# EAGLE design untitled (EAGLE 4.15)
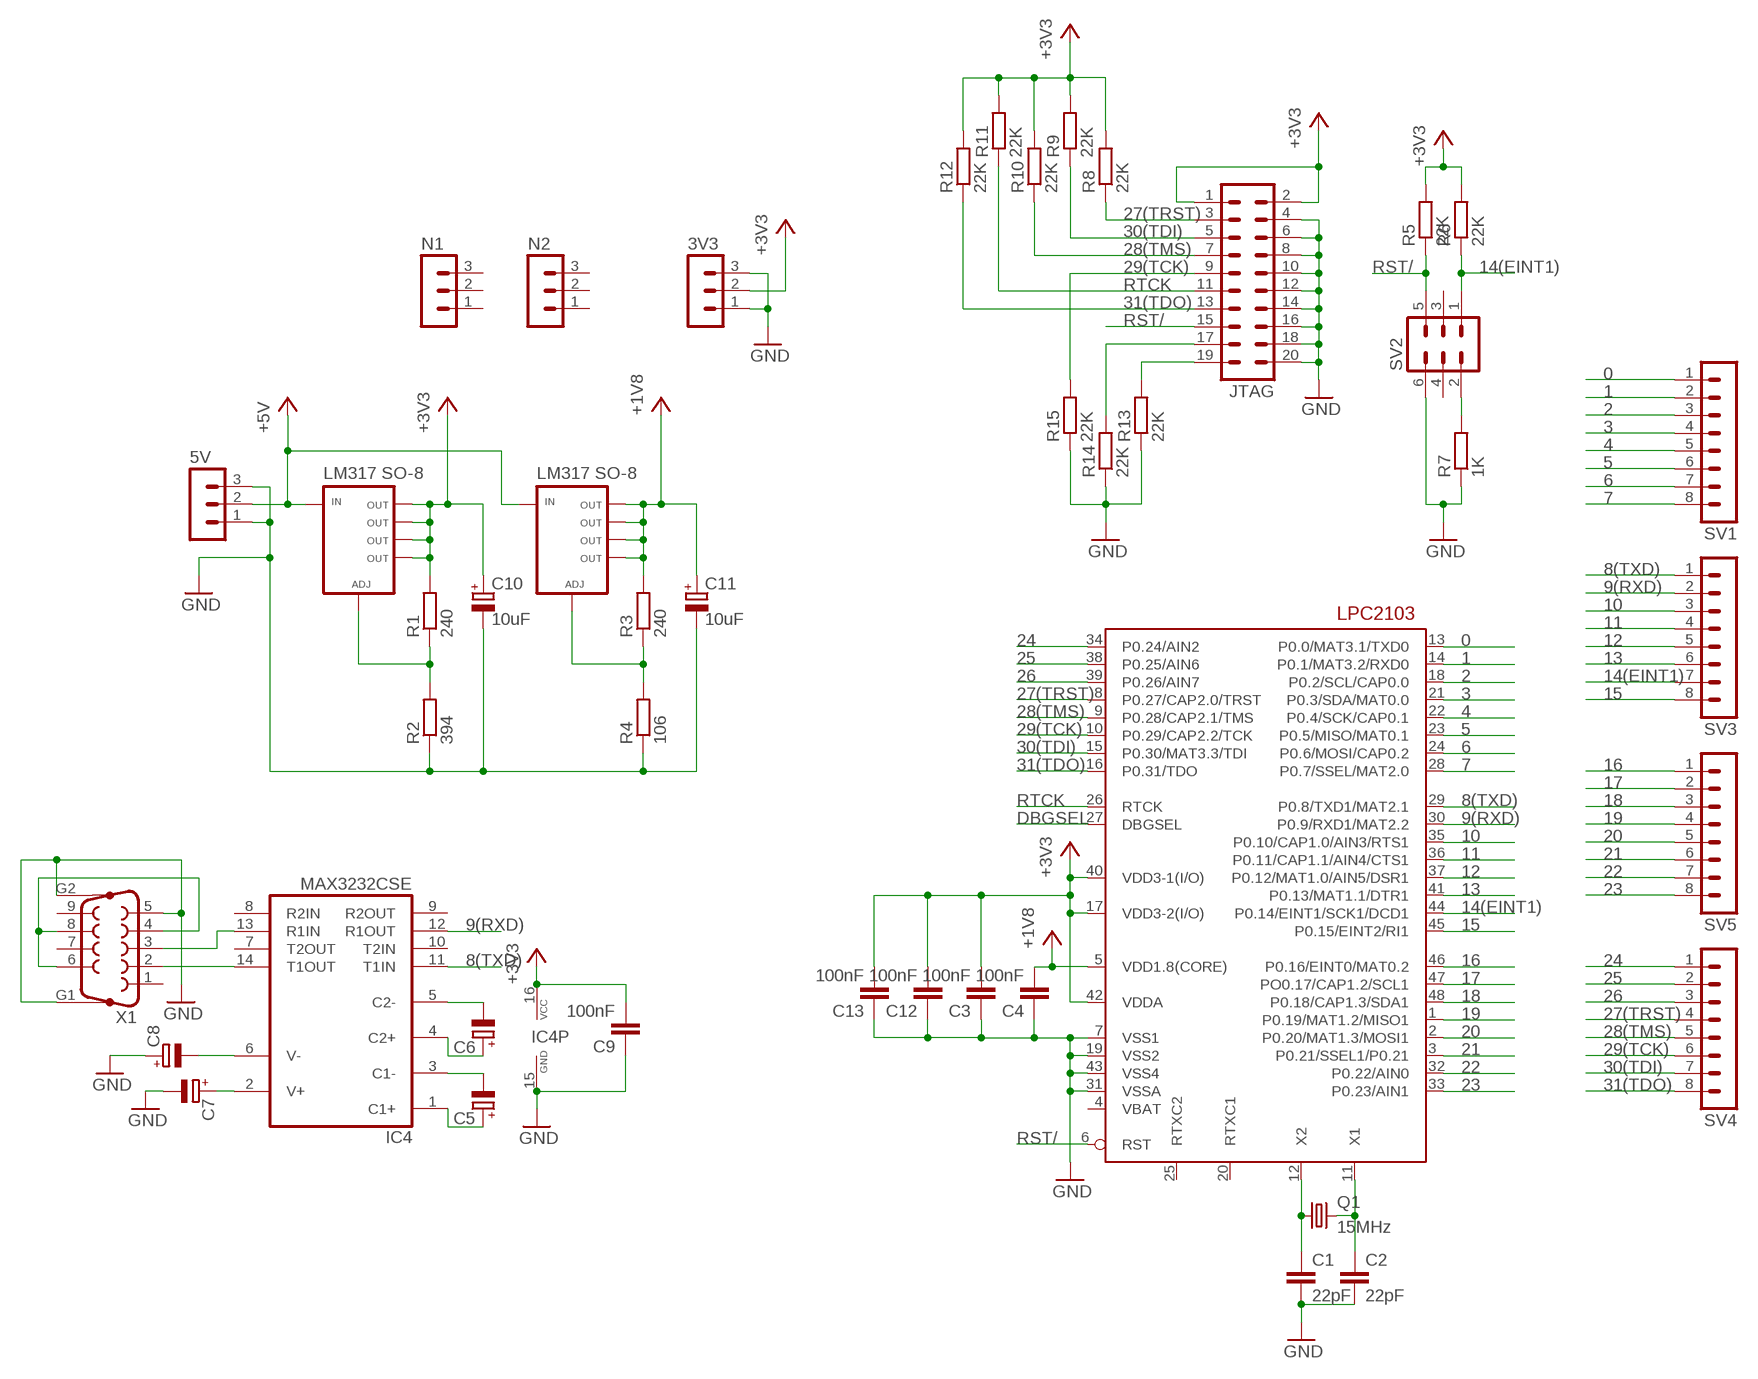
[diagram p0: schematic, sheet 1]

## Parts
3V3  MA03-1  [MA03-1]
5V  MA03-1  [MA03-1]
C1  22pF  C-EUC1206  [C1206]
C2  22pF  C-EUC1206  [C1206]
C3  100nF  C-EUC1206  [C1206]
C4  100nF  C-EUC1206  [C1206]
C5  CPOL-EUE2.5-5  [E2,5-5]
C6  CPOL-EUE2.5-5  [E2,5-5]
C7  CPOL-EUE2.5-5  [E2,5-5]
C8  CPOL-EUE2.5-5  [E2,5-5]
C9  100nF  C-EUC1206  [C1206]
C10  10uF  CPOL-EUE2.5-5  [E2,5-5]
C11  10uF  CPOL-EUE2.5-5  [E2,5-5]
C12  100nF  C-EUC1206  [C1206]
C13  100nF  C-EUC1206  [C1206]
IC1  LPC2103ROUND  [LQFP48ROUND]
IC4  MAX3232CSE  [SO16]
JTAG  MA10-2  [MA10-2]
N1  MA03-1  [MA03-1]
N2  MA03-1  [MA03-1]
Q1  15MHz  CRYTALHC49S  [HC49/S]
R1  240  R-EU_M1206  [M1206]
R2  394  R-EU_M1206  [M1206]
R3  240  R-EU_M1206  [M1206]
R4  106  R-EU_M1206  [M1206]
R5  22K  R-EU_M1206  [M1206]
R6  22K  R-EU_M1206  [M1206]
R7  1K  R-EU_M1206  [M1206]
R8  22K  R-EU_M1206  [M1206]
R9  22K  R-EU_M1206  [M1206]
R10  22K  R-EU_M1206  [M1206]
R11  22K  R-EU_M1206  [M1206]
R12  22K  R-EU_M1206  [M1206]
R13  22K  R-EU_M1206  [M1206]
R14  22K  R-EU_M1206  [M1206]
R15  22K  R-EU_M1206  [M1206]
SV1  MA08-1  [MA08-1]
SV2  MA03-2  [MA03-2]
SV3  MA08-1  [MA08-1]
SV4  MA08-1  [MA08-1]
SV5  MA08-1  [MA08-1]
U$2  LM317  [SO-8]
U$3  LM317  [SO-8]
X1  F09HP  [F09HP]

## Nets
0: IC1.13(P0.0/MAT3.1/TXD0) SV1.1
1: IC1.14(P0.1/MAT3.2/RXD0) SV1.2
2: IC1.18(P0.2/SCL/CAP0.0) SV1.3
3: IC1.21(P0.3/SDA/MAT0.0) SV1.4
4: IC1.22(P0.4/SCK/CAP0.1) SV1.5
5: IC1.23(P0.5/MISO/MAT0.1) SV1.6
6: IC1.24(P0.6/MOSI/CAP0.2) SV1.7
7: IC1.28(P0.7/SSEL/MAT2.0) SV1.8
8(TXD): IC1.29(P0.8/TXD1/MAT2.1) IC4.11(T1IN) SV3.1
9(RXD): IC1.30(P0.9/RXD1/MAT2.2) IC4.12(R1OUT) SV3.2
10: IC1.35(P0.10/CAP1.0/AIN3/RTS1) SV3.3
11: IC1.36(P0.11/CAP1.1/AIN4/CTS1) SV3.4
12: IC1.37(P0.12/MAT1.0/AIN5/DSR1) SV3.5
13: IC1.41(P0.13/MAT1.1/DTR1) SV3.6
14(EINT1): IC1.44(P0.14/EINT1/SCK1/DCD1) R6.1 SV2.1 SV3.7
15: IC1.45(P0.15/EINT2/RI1) SV3.8
16: IC1.46(P0.16/EINT0/MAT0.2) SV5.1
17: IC1.47(PO0.17/CAP1.2/SCL1) SV5.2
18: IC1.48(P0.18/CAP1.3/SDA1) SV5.3
19: IC1.1(P0.19/MAT1.2/MISO1) SV5.4
20: IC1.2(P0.20/MAT1.3/MOSI1) SV5.5
21: IC1.3(P0.21/SSEL1/P0.21) SV5.6
22: IC1.32(P0.22/AIN0) SV5.7
23: IC1.33(P0.23/AIN1) SV5.8
24: IC1.34(P0.24/AIN2) SV4.1
25: IC1.38(P0.25/AIN6) SV4.2
26: IC1.39(P0.26/AIN7) SV4.3
27(TRST): IC1.8(P0.27/CAP2.0/TRST) JTAG.3 R8.1 SV4.4
28(TMS): IC1.9(P0.28/CAP2.1/TMS) JTAG.7 R10.1 SV4.5
29(TCK): IC1.10(P0.29/CAP2.2/TCK) JTAG.9 R15.2 SV4.6
30(TDI): IC1.15(P0.30/MAT3.3/TDI) JTAG.5 R9.1 SV4.7
31(TDO): IC1.16(P0.31/TDO) JTAG.13 R12.1 SV4.8
+1V8: C4.2 C11.+ IC1.5(VDD1.8(CORE)) R3.2 U$3.2(OUT) U$3.3(OUT1) U$3.6(OUT2) U$3.7(OUT3)
+3V3: 3V3.2 C3.2 C9.2 C10.+ C12.2 C13.2 IC1.17(VDD3-2(I/O)) IC1.40(VDD3-1(I/O)) IC1.42(VDDA) IC4.16(VCC) JTAG.1 JTAG.2 R1.2 R5.2 R6.2 R8.2 R9.2 R10.2 R11.2 R12.2 U$2.2(OUT) U$2.3(OUT1) U$2.6(OUT2) U$2.7(OUT3)
+5V: 5V.2 U$2.1(IN) U$3.1(IN)
DBGSEL: IC1.27(DBGSEL)
GND: 3V3.1 3V3.3 5V.1 5V.3 C1.2 C2.2 C3.1 C4.1 C7.- C8.+ C9.1 C10.- C11.- C12.1 C13.1 IC1.7(VSS1) IC1.19(VSS2) IC1.31(VSSA) IC1.43(VSS4) IC4.15(GND) JTAG.4 JTAG.6 JTAG.8 JTAG.10 JTAG.12 JTAG.14 JTAG.16 JTAG.18 JTAG.20 R2.1 R4.1 R7.1 R13.1 R14.1 R15.1 SV2.6 X1.5 X1.G1 X1.G2
GND.: JTAG.17 R14.2
GND..: JTAG.19 R13.2
N$1: C1.1 IC1.12(X2) Q1.1
N$2: C2.1 IC1.11(X1) Q1.2
N$5: R3.1 R4.2 U$3.4(ADJ)
N$6: C5.+ IC4.1(C1+)
N$7: R1.1 R2.2 U$2.4(ADJ)
N$8: C5.- IC4.3(C1-)
N$9: C6.- IC4.5(C2-)
N$10: C6.+ IC4.4(C2+)
N$11: C8.- IC4.6(V-)
N$12: C7.+ IC4.2(V+)
N$13: IC4.14(T1OUT) X1.2
N$14: IC4.13(R1IN) X1.3
N$15: X1.4 X1.6 X1.8
N$19: R7.2 SV2.2
RST/: IC1.6(RST) JTAG.15 R5.1 SV2.5
RTCK: IC1.26(RTCK) JTAG.11 R11.1
Unconnected: IC1.4(VBAT) IC1.20(RTXC1) IC1.25(RTXC2) IC4.7(T2OUT) IC4.8(R2IN) IC4.9(R2OUT) IC4.10(T2IN) N1.1 N1.2 N1.3 N2.1 N2.2 N2.3 SV2.3 SV2.4 X1.1 X1.7 X1.9

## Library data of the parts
3V3 5V N1 N2 = con-lstb:MA03-1: PIN HEADER
C1-C4 C9 C12 C13 = rcl:C-EU: CAPACITOR, European symbol
C5-C8 C10 C11 = rcl:CPOL-EU: POLARIZED CAPACITOR, European symbol
IC1 = nxp:LPC2103: LPC2101/2102/2103 microcontroler from Philips
IC4 = maxim:MAX3232*: True RS-232 Transceivers 3.0V to 5.5V, Low-Power up to 1Mbps, Using Four 0.1µF External Capacitors Source: http://pdfserv.maxim-ic.com/en/ds/MAX3222-MAX3241.pdf
JTAG = con-lstb:MA10-2: PIN HEADER
Q1 = crystal:CRYTAL: CRYSTAL
R1-R15 = rcl:R-EU_: RESISTOR, European symbol
SV1 SV3-SV5 = con-lstb:MA08-1: PIN HEADER
SV2 = con-lstb:MA03-2: PIN HEADER
U$2 U$3 = Steffi:LM317
X1 = con-subd:F09HP: SUB-D

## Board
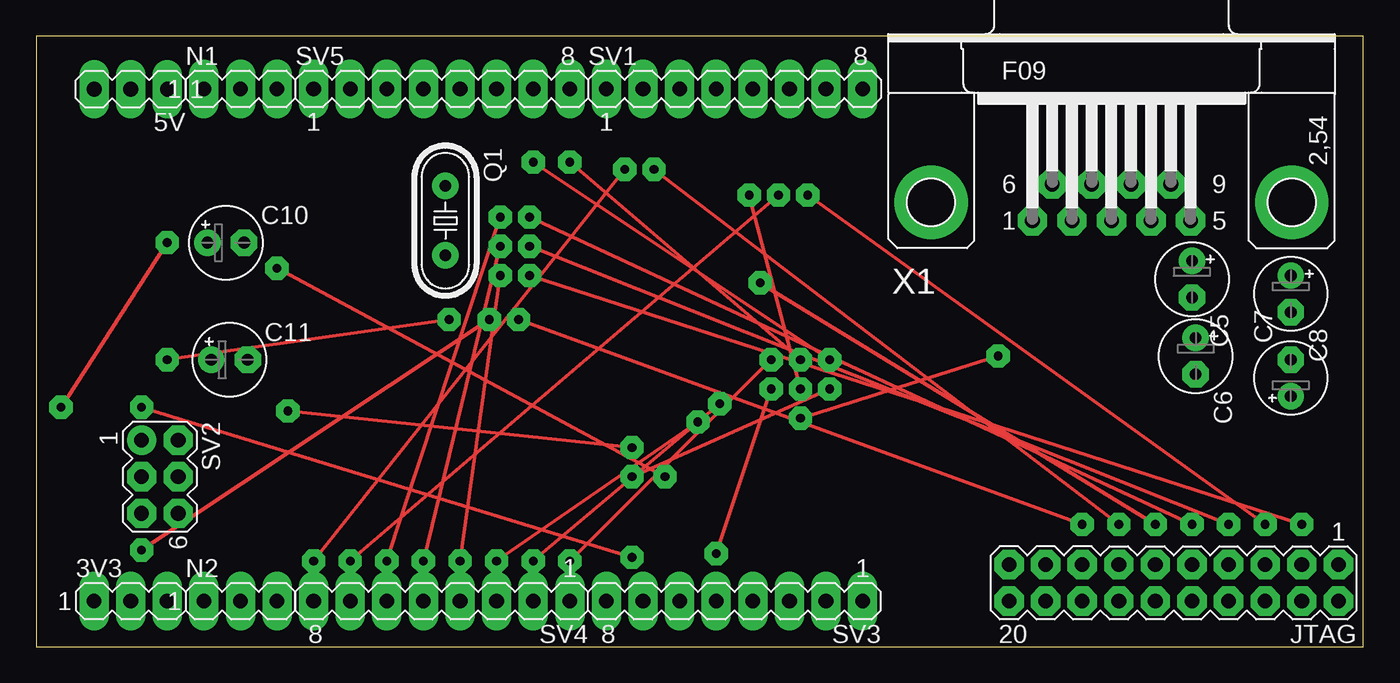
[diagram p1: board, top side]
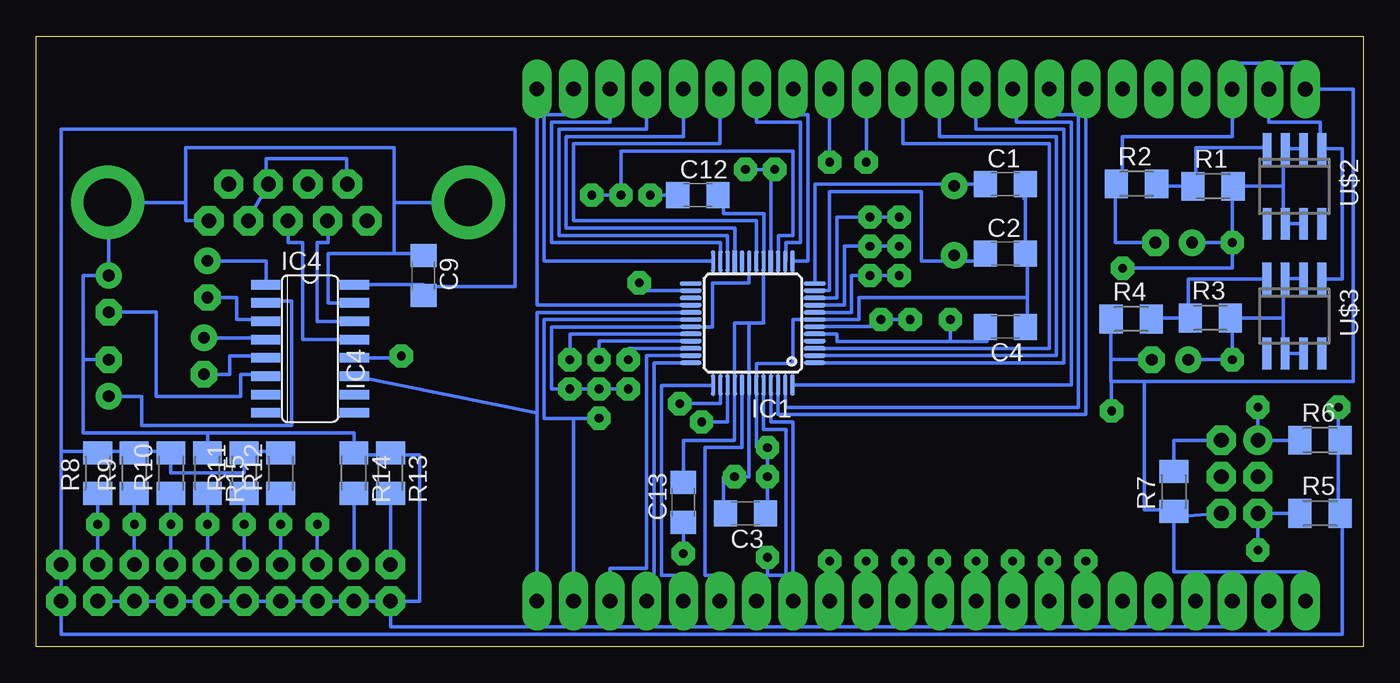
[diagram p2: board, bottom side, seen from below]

Size 92.13 x 42.41 mm. Coordinates in mm from the lower left corner, seen from the top.
Outline: 0,0 92.13,0 92.13,42.41 0,42.41 0,0
Copper layers (1*16): Top 0.035mm / dielectric 1.5mm / Bottom 0.035mm
Design rules "default": minimum track width 10mil, minimum drill 24mil, track to track 8mil, track to pad 8mil, pad to pad 8mil, via to via 8mil, smd to smd 8mil, copper to edge 10mil, drill to drill 10mil, minimum pad ring 20mil, minimum via ring 20mil, stop-mask expansion 4mil, vias tented up to drill 0mil, thermal gap 10mil

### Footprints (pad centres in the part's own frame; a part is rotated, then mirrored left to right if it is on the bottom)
MA03-1 = drill 1.016 long: 1 -2.54,0; 2 0,0; 3 2.54,0
C1206 = smd 1.6 x 1.8: 1 -1.4,0; 2 1.4,0
E2,5-5 = drill 0.813 pad 1.6 round: + -1.27,0 | drill 0.813 pad 1.6 octagon: - 1.27,0
LQFP48ROUND = smd 1.5 x 0.3: 1 -4.3,2.75; 2 -4.3,2.25; 3 -4.3,1.75; 4 -4.3,1.25; 5 -4.3,0.75; 6 -4.3,0.25; 7 -4.3,-0.25; 8 -4.3,-0.75; 9 -4.3,-1.25; 10 -4.3,-1.75; 11 -4.3,-2.25; 12 -4.3,-2.75; 25 4.3,-2.75; 26 4.3,-2.25; 27 4.3,-1.75; 28 4.3,-1.25; 29 4.3,-0.75; 30 4.3,-0.25; 31 4.3,0.25; 32 4.3,0.75; 33 4.3,1.25; 34 4.3,1.75; 35 4.3,2.25; 36 4.3,2.75 | smd 0.3 x 1.5: 13 -2.75,-4.3; 14 -2.25,-4.3; 15 -1.75,-4.3; 16 -1.25,-4.3; 17 -0.75,-4.3; 18 -0.25,-4.3; 19 0.25,-4.3; 20 0.75,-4.3; 21 1.25,-4.3; 22 1.75,-4.3; 23 2.25,-4.3; 24 2.75,-4.3; 37 2.75,4.3; 38 2.25,4.3; 39 1.75,4.3; 40 1.25,4.3; 41 0.75,4.3; 42 0.25,4.3; 43 -0.25,4.3; 44 -0.75,4.3; 45 -1.25,4.3; 46 -1.75,4.3; 47 -2.25,4.3; 48 -2.75,4.3
SO16 = smd 0.66 x 2.032: 1 -4.445,-3.073; 2 -3.175,-3.073; 3 -1.905,-3.073; 4 -0.635,-3.073; 5 0.635,-3.073; 6 1.905,-3.073; 7 3.175,-3.073; 8 4.445,-3.073; 9 4.445,3.073; 10 3.175,3.073; 11 1.905,3.073; 12 0.635,3.073; 13 -0.635,3.073; 14 -1.905,3.073; 15 -3.175,3.073; 16 -4.445,3.073
MA10-2 = drill 1.016 octagon: 1 -11.43,-1.27; 2 -11.43,1.27; 3 -8.89,-1.27; 4 -8.89,1.27; 5 -6.35,-1.27; 6 -6.35,1.27; 7 -3.81,-1.27; 8 -3.81,1.27; 9 -1.27,-1.27; 10 -1.27,1.27; 11 1.27,-1.27; 12 1.27,1.27; 13 3.81,-1.27; 14 3.81,1.27; 15 6.35,-1.27; 16 6.35,1.27; 17 8.89,-1.27; 18 8.89,1.27; 19 11.43,-1.27; 20 11.43,1.27
HC49/S = drill 0.813 round: 1 -2.413,0; 2 2.413,0
M1206 = smd 1.6 x 2: 1 -1.4,0; 2 1.4,0
MA08-1 = drill 1.016 long: 1 -8.89,0; 2 -6.35,0; 3 -3.81,0; 4 -1.27,0; 5 1.27,0; 6 3.81,0; 7 6.35,0; 8 8.89,0
MA03-2 = drill 1.016 round: 1 -2.54,-1.27 | drill 1.016 octagon: 2 -2.54,1.27; 3 0,-1.27; 4 0,1.27; 5 2.54,-1.27; 6 2.54,1.27
SO-8 = smd 0.6 x 2.2: 1 -1.905,-2.6; 2 -0.635,-2.6; 3 0.635,-2.6; 4 1.905,-2.6; 5 1.905,2.6; 6 0.635,2.6; 7 -0.635,2.6; 8 -1.905,2.6
F09HP = drill 1.016 octagon: 1 -5.486,-1.27; 2 -2.743,-1.27; 3 0,-1.27; 4 2.743,-1.27; 5 5.486,-1.27; 6 -4.115,1.27; 7 -1.372,1.27; 8 1.372,1.27; 9 4.115,1.27 | drill 3.302 pad 5.08 round: G1 -12.522,0; G2 12.522,0

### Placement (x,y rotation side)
3V3  6.57,3.17 0 top
5V  6.57,38.71 180 top
C1  24.85,32.13 0 bottom
C2  24.85,27.3 0 bottom
C3  42.89,9.27 180 bottom
C4  24.85,22.22 180 bottom
C5  80.23,25.52 270 top
C6  80.48,20.19 270 top
C7  87.08,18.66 90 top
C8  87.08,24.51 270 top
C9  65.24,25.78 270 bottom
C10  13.17,28.06 0 top
C11  13.42,19.93 0 top
C12  46.19,31.36 0 bottom
C13  47.21,10.03 90 bottom
IC1  42.38,22.47 180 bottom
IC4  73.11,20.7 270 bottom
JTAG  78.96,4.44 180 top
N1  14.19,38.73 0 top
N2  14.19,3.17 0 top
Q1  28.41,29.59 270 top
R1  10.45,31.97 0 bottom
R2  15.76,32.14 0 bottom
R3  10.63,22.83 0 bottom
R4  16.12,22.75 0 bottom
R5  3.01,9.27 0 bottom
R6  3.01,14.35 0 bottom
R7  13.17,10.79 90 bottom
R8  87.85,12.06 90 bottom
R9  85.31,12.06 90 bottom
R10  82.77,12.06 90 bottom
R11  77.69,12.06 90 bottom
R12  75.15,12.06 90 bottom
R13  67.53,12.06 270 bottom
R14  70.07,12.06 270 bottom
R15  80.23,12.06 270 bottom
SV1  48.48,38.73 0 top
SV2  8.6,11.81 270 top
SV3  48.48,3.17 180 top
SV4  28.16,3.17 180 top
SV5  28.16,38.73 0 top
U$2  4.8,31.98 180 bottom
U$3  4.8,22.97 180 bottom
X1  74.64,30.86 0 top

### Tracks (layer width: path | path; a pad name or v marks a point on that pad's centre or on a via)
0
  Bottom 0.254: 39.63,38.73 SV1.1 39.59,36.95 38.57,36.95 38.57,26.77 IC1.13
1
  Bottom 0.254: SV1.2 42.13,36.44 39.08,36.44 39.08,28.06 40.09,28.06 40.09,26.77 IC1.14
2
  Bottom 0.254: IC1.18 42.13,29.59 54.83,29.59 54.83,34.92 44.67,34.92 SV1.3
3
  Bottom 0.254: IC1.21 43.63,29.08 55.33,29.08 55.33,35.43 47.21,35.43 SV1.4
4
  Bottom 0.254: IC1.22 44.13,28.57 55.84,28.57 55.84,35.94 49.75,35.94 SV1.5 49.75,38.98
5
  Bottom 0.254: IC1.23 44.63,28.06 56.35,28.06 56.35,36.44 52.29,36.44 SV1.6
6
  Bottom 0.254: IC1.24 45.13,26.79 56.86,26.79 56.86,36.95 54.83,36.95 SV1.7
7
  Bottom 0.254: IC1.28 57.37,23.72 SV1.8
8(TXD)
  Bottom 0.254: IC1.29 57.37,23.22 57.37,16.12 | SV3.1 57.37,16.12 | IC4.11 57.37,16.25 57.37,16.12
9(RXD)  (via drill 0.6)
  Top 0.254: v53.05,15.87 v66.76,20.19
  Bottom 0.254: IC1.30 56.35,22.72 56.35,22.73 56.86,22.73 56.86,15.87 54.83,15.87 | SV3.2 54.83,15.87 | IC4.12 66.76,20.06 v66.76,20.19 | 54.83,15.87 v53.05,15.87
10
  Bottom 0.254: IC1.35 49.75,20.22 49.75,5.46 52.29,5.46 SV3.3
11
  Bottom 0.254: IC1.36 49.24,19.72 49.24,4.95 49.75,4.95 SV3.4
12
  Bottom 0.254: IC1.37 45.13,18.16 48.73,18.16 48.73,4.95 47.21,4.95 SV3.5
13
  Bottom 0.254: IC1.41 43.13,13.84 45.68,13.84 45.68,4.95 44.92,4.95 44.92,3.17 SV3.6
14(EINT1)  (via drill 0.6 pad 0.25)
  Top 0.254: v7.33,16.63 v41.36,6.22
  Bottom 0.254: R6.1 SV2.1 v7.33,16.63 | IC1.44 41.63,15.11 40.09,15.11 40.09,4.95 41.36,4.95 | 41.36,4.95 42.13,4.95 SV3.7 | v41.36,6.22 41.36,4.95
15
  Bottom 0.254: IC1.45 41.13,15.62 39.59,15.62 SV3.8
16
  Bottom 0.254: IC1.46 40.63,16.12 19.27,16.12 SV5.1
17
  Bottom 0.254: IC1.47 40.13,16.63 19.77,16.63 19.77,36.95 21.81,36.95 SV5.2
18
  Bottom 0.254: IC1.48 20.28,18.17 20.28,36.44 24.09,36.44 24.09,38.73 SV5.3
19
  Bottom 0.254: IC1.1 20.79,19.72 20.79,35.94 26.89,35.94 SV5.4
20
  Bottom 0.254: IC1.2 21.3,20.22 21.3,35.43 29.43,35.43 SV5.5
21
  Bottom 0.254: IC1.3 31.97,20.72 30.44,20.7 21.81,20.7 21.81,34.92 31.97,34.92 SV5.6
22  (via drill 0.6)
  Top 0.254: v55.08,19.93 v34.51,33.65
  Bottom 0.254: IC1.32 55.08,21.71 v55.08,19.93 | v34.51,33.65 SV5.7
23  (via drill 0.6)
  Top 0.254: v53.05,19.93 v37.05,33.65
  Bottom 0.254: IC1.33 53.05,21.22 v53.05,19.93 | v37.05,33.65 SV5.8
24  (via drill 0.6)
  Top 0.254: v37.05,5.96 v51.02,19.93
  Bottom 0.254: IC1.34 51.02,20.72 v51.02,19.93 | SV4.1 v37.05,5.96
25  (via drill 0.6)
  Top 0.254: v34.51,5.96 v47.46,16.89
  Bottom 0.254: 34.51,2.92 SV4.2 v34.51,5.96 | IC1.38 44.63,16.89 v47.46,16.89
26  (via drill 0.6)
  Top 0.254: v31.97,5.96 v45.94,15.62
  Bottom 0.254: IC1.39 44.13,15.62 v45.94,15.62 | SV4.3 v31.97,5.96
27(TRST)  (via drill 0.6)
  Top 0.254: v29.43,5.96 v32.22,25.78 | v34.25,25.78 v87.85,8.5
  Bottom 0.254: JTAG.3 v87.85,8.5 R8.1 | SV4.4 v29.43,5.96 | IC1.8 35.52,23.22 35.52,25.78 v34.25,25.78 v32.22,25.78
28(TMS)  (via drill 0.6)
  Top 0.254: v26.89,5.96 v32.22,27.81 | v34.25,27.81 v82.77,8.5
  Bottom 0.254: JTAG.7 v82.77,8.5 R10.1 | SV4.5 v26.89,5.96 | IC1.9 36.03,23.72 36.03,27.81 v34.25,27.81 v32.22,27.81
29(TCK)  (via drill 0.6)
  Top 0.254: v24.35,5.96 v32.22,29.84 | v34.25,29.84 v80.23,8.5
  Bottom 0.254: JTAG.9 v80.23,8.5 R15.2 | SV4.6 v24.35,5.96 | IC1.10 36.54,24.22 36.54,29.84 v34.25,29.84 v32.22,29.84
30(TDI)  (via drill 0.6)
  Top 0.254: v21.81,5.96 v51.52,31.36 | v53.56,31.36 v85.31,8.5
  Bottom 0.254: v85.31,8.5 JTAG.5 | SV4.7 v21.81,5.96 | v85.31,8.5 R9.1 v85.31,8.5 | v53.56,31.36 v51.52,31.36 51.52,34.41 39.59,34.41 39.59,28.57 40.6,28.57 40.6,26.77 IC1.15
31(TDO)  (via drill 0.6)
  Top 0.254: v19.27,5.96 v40.86,33.14 | v42.89,33.14 v75.15,8.5
  Bottom 0.254: JTAG.13 v75.15,8.5 R12.1 | 41.13,33.14 IC1.16 | 41.13,33.14 v42.89,33.14 | SV4.8 v19.27,5.96 | v40.86,33.14 41.13,33.14
+1V8  (via drill 0.6, 0.6 pad 0.25)
  Top 0.254: v9.11,19.93 v28.66,22.73
  Bottom 0.254: U$3.2 U$3.3 5.55,25.57 5.55,22.73 | U$3.7 U$3.6 5.55,20.37 | 5.55,20.37 5.55,20.44 | 5.55,20.37 5.55,22.73 | 5.55,22.73 5.55,22.83 R3.2 9.11,22.83 v9.11,19.93 C11.+ | IC1.5 36.54,21.72 36.54,21.2 28.66,21.2 | C4.2 26.12,22.22 26.12,21.2 28.66,21.2 | v28.66,22.73 28.66,21.2
+3V3  (via drill 0.6)
  Top 0.254: v1.74,16.63 v9.11,28.06 | v16.73,26.28 v43.65,11.81
  Bottom 0.254: U$2.2 U$2.3 5.55,34.57 | U$2.7 U$2.6 5.55,29.38 | 5.55,29.38 5.55,29.33 | 5.55,34.57 5.55,34.67 | 5.55,32.13 5.55,29.38 | 5.55,32.13 5.55,34.57 | 5.55,32.13 5.55,31.97 R1.2 9.11,31.97 v9.11,28.06 | 1.74,14.35 R6.2 | 1.74,14.35 1.74,9.27 R5.2 1.49,9.27 1.49,0.88 6.57,0.88 | 69.81,25.14 69.81,25.27 | 69.81,25.14 IC4.16 | 69.81,25.14 69.81,25.01 | 1.74,14.35 v1.74,16.63 | v9.11,28.06 C10.+ | R12.2 75.15,13.58 77.69,13.58 | 87.85,13.58 85.31,13.58 | 82.77,13.58 R10.2 | 85.31,13.58 R9.2 | 85.31,13.58 82.77,13.58 | 87.85,13.58 R8.2 | 90.39,13.58 87.85,13.58 | 90.39,13.58 JTAG.1 JTAG.2 90.39,0.88 6.57,0.88 | 42.63,22.47 42.63,19.68 42.63,18.41 IC1.42 42.63,22.47 | 42.63,22.47 41.63,22.47 IC1.17 41.62,30.09 44.41,30.09 44.41,31.11 C12.2 | 42.63,22.47 | 42.63,22.47 43.65,22.47 43.65,18.16 | 43.65,18.16 43.63,18.16 IC1.40 43.65,18.16 | 65.24,24.25 C9.2 65.24,25.01 | 42.63,22.47 41.62,22.47 | 42.63,22.47 42.63,11.81 v43.65,11.81 44.41,11.81 44.41,9.27 C3.2 | v16.73,26.28 9.11,26.28 v9.11,28.06 | 6.57,0.88 3V3.2 | 82.77,13.58 82.77,12.06 77.69,12.06 77.69,13.58 | 77.69,13.58 R11.2 | 90.39,13.58 90.39,35.94 58.89,35.94 58.89,25.01 65.24,25.01 | 69.81,25.14 65.24,25.14 65.24,25.01 | C13.2 47.21,14.35 43.65,14.35 43.65,18.16
+5V
  Bottom 0.254: U$3.1 2.76,25.57 2.76,25.52 1.49,25.52 1.49,34.57 U$2.1 3.01,34.57 3.01,36.44 6.57,36.44 5V.2 | 5V.2 6.82,38.73 | 5V.2
GND  (via drill 0.6)
  Top 0.254: v17.49,16.38 v41.36,13.84 | v41.36,11.81 v55.08,17.9 | v53.05,17.9 v49.49,31.36 | v51.02,17.9 v47.21,6.47
  Bottom 0.254: 4.03,38.73 5V.3 4.03,38.73 | 4.03,38.73 4.03,40.51 9.11,40.51 9.11,38.73 | IC4.15 71.84,23.87 71.84,27.3 67.27,27.3 | 67.27,30.86 X1.G1 | 79.97,29.59 X1.5 81.75,29.59 81.75,30.86 | 67.78,3.17 JTAG.18 JTAG.16 JTAG.14 JTAG.12 JTAG.10 | JTAG.10 JTAG.8 JTAG.6 JTAG.4 | 13.17,9.01 SV2.6 | 17.23,22.75 R4.1 17.52,19.93 | 17.52,19.93 17.52,18.41 17.49,18.41 | 15.2,18.41 0.72,18.41 0.72,38.73 4.03,38.73 | 15.2,18.41 17.49,18.41 | 13.17,9.52 R7.1 13.17,9.01 | 87.08,30.86 C8.+ 88.86,25.78 88.86,19.93 | 81.75,30.86 81.75,34.67 67.27,34.67 67.27,30.86 | 67.27,30.86 67.27,27.3 | 13.17,9.52 15.2,9.52 15.2,18.41 | 13.17,9.01 13.17,9.52 | 17.23,32.13 17.16,32.13 R2.1 | 87.08,30.86 arc-180 X1.G2 | 87.08,30.86 81.75,30.86 | R2.1 16.73,32.14 16.73,35.43 9.11,35.43 9.11,38.73 | 9.11,38.73 5V.1 | 17.52,19.93 C11.- | 70.07,13.33 R14.1 70.07,14.85 80.23,14.85 | R13.1 67.53,13.33 70.07,13.33 | JTAG.10 80.23,3.42 | 67.78,3.17 JTAG.10 | 17.23,32.13 17.23,32.14 R2.1 | C10.- 17.23,28.06 17.23,32.13 | C2.2 C1.2 23.58,31.11 | IC1.7 39.59,22.73 | IC1.43 42.13,18.16 42.13,19.68 | IC1.19 42.63,25.27 45.17,25.27 45.17,22.22 | IC1.31 | IC1.31 45.17,22.22 | C9.1 65.49,27.18 65.49,27.3 67.27,27.3 | 56.35,22.22 IC1.31 | 56.35,22.22 56.35,17.9 v55.08,17.9 v53.05,17.9 v51.02,17.9 | 39.59,22.73 IC1.7 | 39.59,22.73 39.59,19.68 42.13,19.68 | 42.13,19.68 42.13,13.84 v41.36,13.84 v41.36,11.81 41.36,9.27 C3.1 | 17.49,18.41 v17.49,16.38 | 56.35,22.22 45.17,22.22 | 88.86,19.93 C7.- | C2.2 23.58,27.3 | IC1.7 38.06,22.72 38.06,22.73 35.01,22.73 35.01,24.25 23.33,24.25 | C2.2 23.33,27.3 23.33,24.25 | 3V3.1 4.03,5.2 9.11,5.2 | 9.11,5.2 3V3.3 9.36,1.39 67.53,1.39 JTAG.20 67.78,3.17
  Bottom 0.254: 70.07,13.33 65.49,13.33 65.49,3.17 67.78,3.17 | 80.23,14.85 R15.1 | 80.23,14.85 88.86,14.85 88.86,19.93 | 13.17,9.01 13.17,5.2 9.11,5.2 | C4.1 23.33,22.22 23.33,24.25 | v49.49,31.36 C12.1 | v47.21,6.47 C13.1
GND.
  Bottom 0.254: JTAG.17 R14.2
GND..
  Bottom 0.254: JTAG.19 R13.2
N$1
  Bottom 0.254: C1.1 28.41,32.13 | 28.41,32.13 Q1.1 | IC1.12 38.06,25.22 38.06,32.13 28.41,32.13
N$2
  Bottom 0.254: C2.1 26.25,26.79 28.41,26.79 | 28.41,26.79 Q1.2 | 28.41,26.79 30.7,26.79 30.7,31.62 37.05,31.62 37.05,24.72 IC1.11
N$5
  Bottom 0.254: 14.69,22.75 14.69,22.73 | 14.69,22.75 R4.2 | 14.69,22.75 14.69,22.83 R3.1 12.15,22.83 12.15,25.52 6.82,25.52 6.82,25.57 U$3.4
N$6
  Bottom 0.254: IC4.1 76.16,25.14 76.16,26.79 C5.+
N$7
  Bottom 0.254: U$2.4 6.82,34.57 6.82,34.67 11.65,34.67 11.65,31.97 R1.1 14.19,31.97 | 14.19,31.97 14.19,32.14 R2.2 | 14.19,31.97 14.19,31.87
N$8
  Bottom 0.254: C5.- 78.19,24.25 78.19,22.73 76.16,22.73 76.16,22.6 IC4.3
N$9
  Bottom 0.254: C6.- 78.7,18.92 78.7,20.19 76.16,20.19 76.16,20.06 IC4.5
N$10
  Bottom 0.254: IC4.4 76.16,21.33 76.16,21.46 C6.+
N$11
  Bottom 0.254: C8.- 83.78,23.24 83.78,17.39 77.94,17.39 77.94,18.92 76.16,18.92 76.16,18.79 IC4.6
N$12
  Bottom 0.254: IC4.2 76.16,23.87 76.16,24 74.38,24 74.38,15.36 84.8,15.36 84.8,17.39 C7.+
N$13
  Bottom 0.254: IC4.14 72.61,22.6 72.61,28.06 71.84,28.06 71.84,29.59 X1.2
N$14
  Bottom 0.254: IC4.13 73.62,21.33 73.62,28.06 74.64,28.06 X1.3
N$15
  Bottom 0.254: X1.6 70.57,32.13 70.57,33.9 76.16,33.9 76.16,32.13 X1.8 77.43,29.59
  Bottom 0.406: 77.43,29.59 X1.4
N$19
  Bottom 0.254: SV2.2 13.17,14.35 R7.2
RST/  (via drill 0.6)
  Top 0.254: v7.33,6.73 v31.46,22.73 | v33.49,22.73 v72.61,8.5
  Bottom 0.254: R5.1 SV2.5 v7.33,6.73 | v72.61,8.5 JTAG.15 | IC1.6 33.49,22.22 v33.49,22.73 v31.46,22.73
RTCK  (via drill 0.6)
  Top 0.254: v50.25,25.27 v77.69,8.5
  Bottom 0.254: JTAG.11 v77.69,8.5 R11.1 | IC1.26 50.25,24.72 v50.25,25.27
